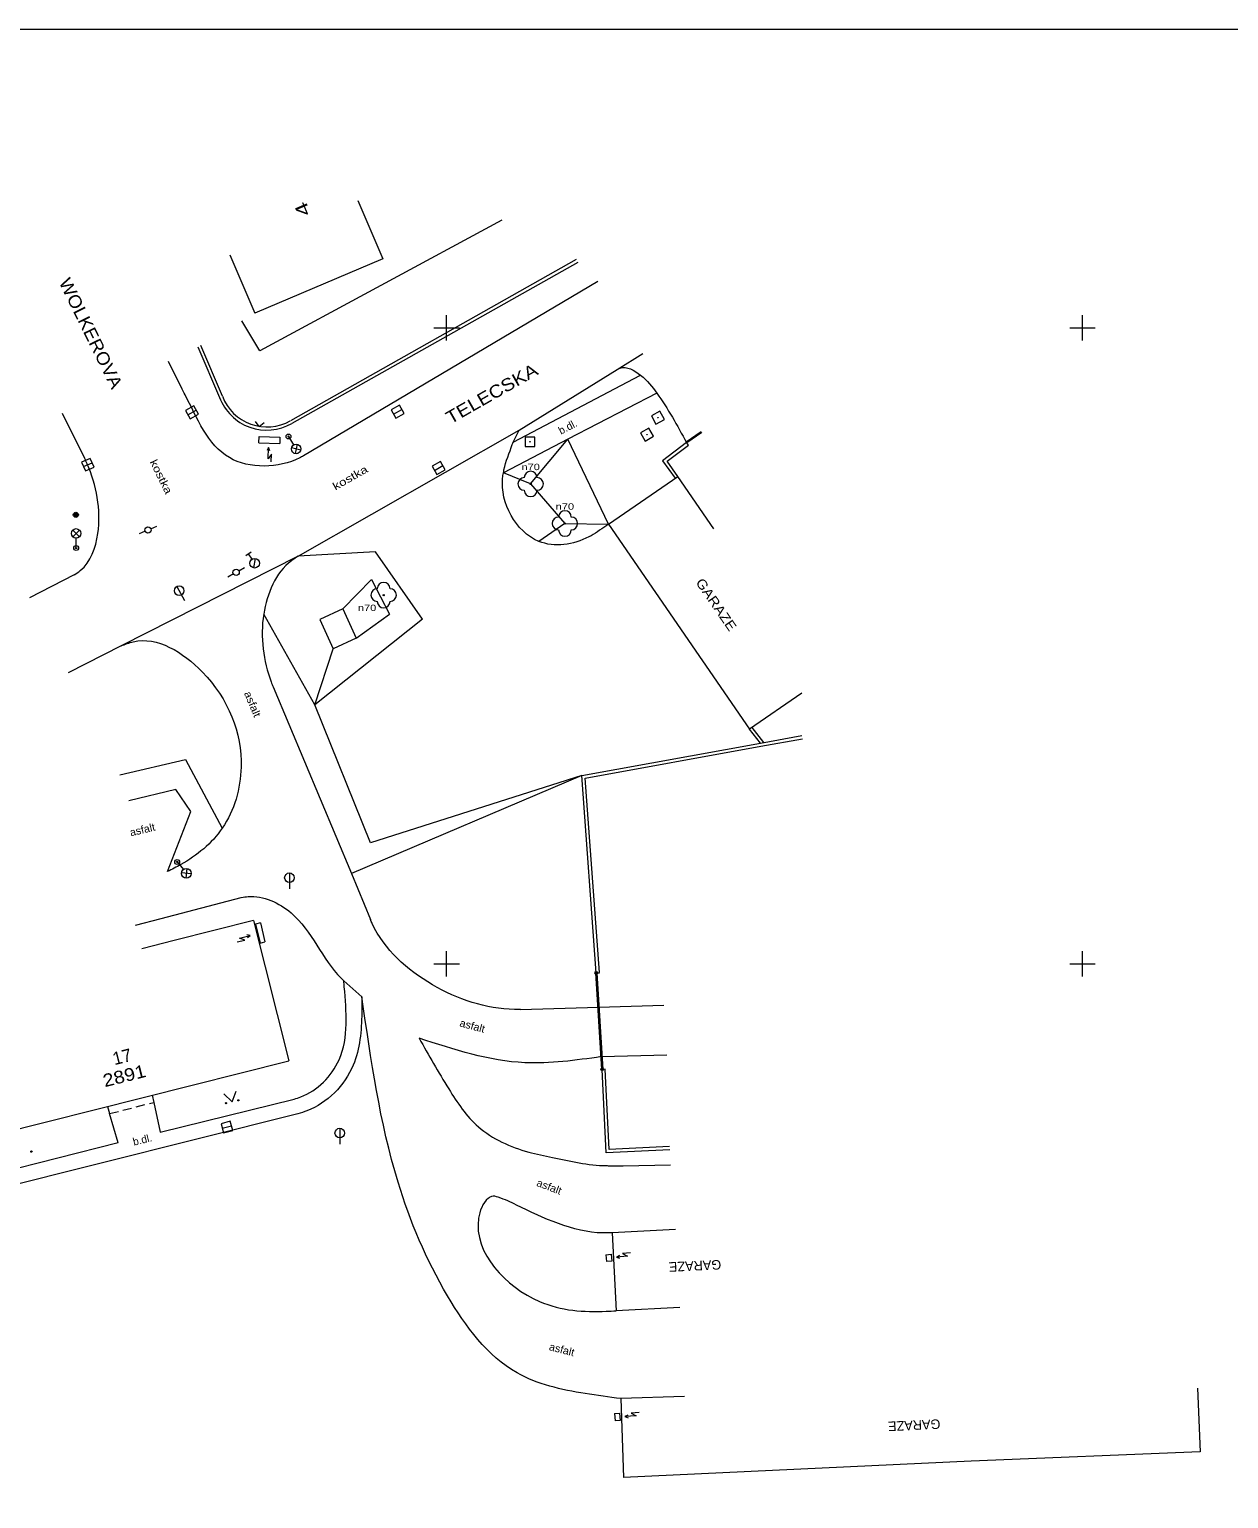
# Model space of a CAD drawing. Extents: x -670514 to -669423, y -1130798 to -1130123.
# Drawn here: x -669732.8 to -669638.5, y -1130592 to -1130476.5 of the extents above; entities that cross this region are included whole.
import ezdxf
from ezdxf.enums import TextEntityAlignment as Align

# ---------------------------------------------------------------- set-up
doc = ezdxf.new("R2010")
doc.units = 0
doc.header["$LTSCALE"] = 0.24
doc.linetypes.add('MEDIUM_DASHED', pattern=[4.5, 3, -1.5])
for name, color, linetype, lineweight in [('10', 7, 'Continuous', 13), ('11', 7, 'Continuous', 13), ('14', 7, 'Continuous', 13), ('22', 7, 'Continuous', 13), ('24', 7, 'Continuous', 13), ('25', 7, 'Continuous', 13), ('26', 7, 'Continuous', 13), ('27', 7, 'Continuous', 13), ('28', 7, 'Continuous', 13), ('33', 7, 'Continuous', 13), ('36', 7, 'Continuous', 13), ('45', 7, 'Continuous', 13), ('5', 7, 'Continuous', 13), ('60', 7, 'Continuous', 13), ('61', 7, 'Continuous', 13), ('7', 7, 'Continuous', 13), ('8', 7, 'Continuous', 13)]:
    doc.layers.add(name, color=color, linetype=linetype, lineweight=lineweight)
for name, color, linetype in [('40', 7, 'Continuous'), ('41', 7, 'Continuous'), ('43', 7, 'Continuous'), ('44', 7, 'Continuous')]:
    doc.layers.add(name, color=color, linetype=linetype)

msp = doc.modelspace()

# ---------------------------------------------------------------- linework, layer by layer
at = {"layer": '10'}
for p, q in [((-669688.102, -1130496.354), (-669711.258, -1130510.061)), ((-669720.795, -1130504.819), (-669721.869, -1130502.635)), ((-669694.776, -1130508.979), (-669684.745, -1130503.722)), ((-669728.447, -1130510.274), (-669730.191, -1130506.73)), ((-669694.776, -1130508.979), (-669694.298, -1130508.049)), ((-669729.281, -1130519.412), (-669732.799, -1130521.237)), ((-669708.164, -1130522.099), (-669709.981, -1130522.935)), ((-669709.981, -1130522.935), (-669708.929, -1130525.221)), ((-669708.164, -1130522.099), (-669707.112, -1130524.385)), ((-669725.596, -1130525.002), (-669729.753, -1130527.108)), ((-669707.112, -1130524.385), (-669708.929, -1130525.221)), ((-669722.446, -1130546.433), (-669716.144, -1130544.784)), ((-669724.449, -1130546.957), (-669722.446, -1130546.433)), ((-669706.657, -1130552.601), (-669708.083, -1130551.338)), ((-669694.188, -1130553.588), (-669688.071, -1130553.405)), ((-669688.071, -1130553.405), (-669682.917, -1130553.254)), ((-669687.835, -1130557.295), (-669682.681, -1130557.144)), ((-669723.014, -1130560.889), (-669722.511, -1130563.235)), ((-669722.511, -1130563.235), (-669711.997, -1130560.63)), ((-669711.698, -1130561.786), (-669745.171, -1130570.199)), ((-669725.823, -1130564.08), (-669726.508, -1130561.775)), ((-669725.823, -1130564.08), (-669739.953, -1130567.648)), ((-669686.12, -1130565.865), (-669682.406, -1130565.789))]:
    msp.add_line(p, q, dxfattribs=at)
for points in [[(-669711.663, -1130517.944), (-669694.298, -1130508.049), (-669686.598, -1130503.267), (-669684.585, -1130502.017)], [(-669683.462, -1130505.137), (-669690.477, -1130508.762), (-669695.534, -1130511.41)], [(-669713.646, -1130528.219), (-669707.484, -1130542.904), (-669705.99, -1130546.512)], [(-669721.945, -1130542.74), (-669720.107, -1130538.016), (-669721.296, -1130536.292), (-669724.995, -1130537.187)]]:
    msp.add_lwpolyline(points, dxfattribs=at)
for points in [[(-669686.598, -1130503.267), (-669686.363, -1130503.165), (-669684.745, -1130503.722), (-669683.462, -1130505.137), (-669681.135, -1130509.021)], [(-669711.258, -1130510.061), (-669711.553, -1130510.22), (-669717.079, -1130510.204), (-669720.565, -1130505.253), (-669720.795, -1130504.819)], [(-669695.534, -1130511.41), (-669695.491, -1130511.167), (-669694.837, -1130509.163), (-669694.776, -1130508.979)], [(-669729.281, -1130519.412), (-669728.799, -1130519.083), (-669727.424, -1130516.177), (-669728.268, -1130510.678), (-669728.447, -1130510.274)], [(-669711.663, -1130517.944), (-669712.193, -1130518.304), (-669714.38, -1130522.51), (-669713.792, -1130527.841), (-669713.646, -1130528.219)], [(-669725.596, -1130525.002), (-669724.632, -1130524.675), (-669719.212, -1130527.048), (-669716.159, -1130534.541), (-669717.636, -1130539.328), (-669720.902, -1130542.201), (-669721.945, -1130542.74)], [(-669716.144, -1130544.784), (-669715.597, -1130544.712), (-669712.232, -1130545.988), (-669708.293, -1130551.134), (-669708.083, -1130551.338)], [(-669694.188, -1130553.588), (-669694.674, -1130553.583), (-669701.117, -1130551.645), (-669705.847, -1130546.83), (-669705.99, -1130546.512)], [(-669711.997, -1130560.63), (-669711.461, -1130560.457), (-669708.461, -1130557.551), (-669708.045, -1130551.818), (-669708.083, -1130551.338)], [(-669706.657, -1130552.601), (-669706.669, -1130553.849), (-669707.347, -1130557.964), (-669710.982, -1130561.555), (-669711.698, -1130561.786)], [(-669686.299, -1130584.174), (-669689.11, -1130583.785), (-669694.463, -1130582.153), (-669699.923, -1130576.108), (-669703.819, -1130567.151), (-669706.657, -1130552.601)], [(-669687.835, -1130557.295), (-669693.851, -1130557.774), (-669702.163, -1130555.848)], [(-669702.163, -1130555.848), (-669699.833, -1130559.827), (-669697.503, -1130562.81), (-669693.548, -1130564.792), (-669691.672, -1130565.223), (-669687.451, -1130565.863), (-669687.307, -1130565.865), (-669686.12, -1130565.865)], [(-669686.995, -1130571.148), (-669687.709, -1130571.155), (-669694.508, -1130568.96), (-669695.936, -1130568.345), (-669696.459, -1130568.276), (-669696.717, -1130568.432), (-669697.488, -1130570.002), (-669692.7, -1130576.54), (-669687.448, -1130577.31), (-669686.669, -1130577.271)]]:
    msp.add_spline(points, degree=3, dxfattribs=at)
at = {"layer": '11'}
msp.add_line((-669711.663, -1130517.944), (-669725.596, -1130525.002), dxfattribs=at)
at = {"layer": '14'}
for p, q in [((-669693.393, -1130512.271), (-669690.477, -1130508.762)), ((-669687.272, -1130515.442), (-669690.477, -1130508.762)), ((-669693.393, -1130512.271), (-669695.534, -1130511.41)), ((-669693.393, -1130512.271), (-669690.702, -1130515.38)), ((-669690.702, -1130515.38), (-669692.762, -1130516.783)), ((-669690.702, -1130515.38), (-669687.272, -1130515.442)), ((-669705.896, -1130519.79), (-669708.164, -1130522.099)), ((-669705.896, -1130519.79), (-669704.48, -1130522.5)), ((-669710.365, -1130529.624), (-669714.38, -1130522.51)), ((-669701.907, -1130522.898), (-669710.365, -1130529.624)), ((-669707.112, -1130524.385), (-669704.48, -1130522.5)), ((-669689.367, -1130535.203), (-669707.484, -1130542.904))]:
    msp.add_line(p, q, dxfattribs=at)
for points in [[(-669695.671, -1130491.534), (-669714.69, -1130501.81), (-669716.107, -1130499.438)], [(-669701.907, -1130522.898), (-669705.601, -1130517.602), (-669711.663, -1130517.944)], [(-669689.367, -1130535.203), (-669705.996, -1130540.491), (-669710.365, -1130529.624), (-669708.929, -1130525.221)], [(-669725.686, -1130535.137), (-669720.522, -1130533.934), (-669717.636, -1130539.328)]]:
    msp.add_lwpolyline(points, dxfattribs=at)
msp.add_spline([(-669687.272, -1130515.442), (-669687.476, -1130515.58), (-669688.822, -1130516.433), (-669692.762, -1130516.783), (-669695.596, -1130511.824), (-669695.534, -1130511.41)], degree=3, dxfattribs=at)
at = {"layer": '22'}
for centre in [(-669693.393, -1130512.271), (-669690.702, -1130515.38), (-669704.949, -1130521.011)]:
    msp.add_circle(centre, 0.05, dxfattribs=at)
for centre, start, end in [((-669693.393, -1130511.771), 0, 180), ((-669693.893, -1130512.271), 90, 270), ((-669692.893, -1130512.271), 270, 90), ((-669693.393, -1130512.771), 180, 0), ((-669690.702, -1130514.88), 0, 180), ((-669691.202, -1130515.38), 90, 270), ((-669690.702, -1130515.88), 180, 0), ((-669690.202, -1130515.38), 270, 90), ((-669705.449, -1130521.011), 90, 270), ((-669704.949, -1130520.511), 0, 180), ((-669704.449, -1130521.011), 270, 90), ((-669704.949, -1130521.511), 180, 0)]:
    msp.add_arc(centre, 0.5, start, end, dxfattribs=at)
at = {"layer": '24'}
for p, q in [((-669714.766, -1130509.046), (-669713.125, -1130509.095)), ((-669714.645, -1130546.787), (-669714.282, -1130548.278)), ((-669687.474, -1130572.863), (-669687.422, -1130573.41)), ((-669686.796, -1130585.356), (-669686.76, -1130585.927))]:
    msp.add_line(p, q, dxfattribs=at)
for points in [[(-669714.765, -1130509.046), (-669714.751, -1130508.546), (-669713.11, -1130508.595), (-669713.125, -1130509.094)], [(-669713.901, -1130509.659), (-669714.004, -1130509.411), (-669714.121, -1130509.653)], [(-669713.788, -1130510.544), (-669713.769, -1130509.918), (-669714.03, -1130510.286), (-669714.004, -1130509.411)], [(-669714.645, -1130546.787), (-669715.033, -1130546.881), (-669714.669, -1130548.373), (-669714.282, -1130548.278)], [(-669716.47, -1130548.28), (-669715.861, -1130548.131), (-669716.285, -1130547.977), (-669715.435, -1130547.77)], [(-669715.647, -1130547.935), (-669715.435, -1130547.77), (-669715.699, -1130547.721)], [(-669687.473, -1130572.863), (-669687.075, -1130572.825), (-669687.023, -1130573.372), (-669687.422, -1130573.409)], [(-669685.554, -1130572.705), (-669686.177, -1130572.764), (-669685.78, -1130572.977), (-669686.651, -1130573.06)], [(-669686.418, -1130572.927), (-669686.651, -1130573.06), (-669686.397, -1130573.146)], [(-669684.871, -1130585.271), (-669685.496, -1130585.31), (-669685.106, -1130585.536), (-669685.979, -1130585.591)], [(-669686.795, -1130585.356), (-669686.396, -1130585.33), (-669686.36, -1130585.901), (-669686.76, -1130585.926)], [(-669685.741, -1130585.466), (-669685.979, -1130585.591), (-669685.728, -1130585.685)]]:
    msp.add_lwpolyline(points, dxfattribs=at)
at = {"layer": '25'}
for centre, radius in [((-669729.15, -1130514.7), 0.2), ((-669729.15, -1130514.7), 0.16), ((-669729.15, -1130514.7), 0.12), ((-669729.15, -1130514.7), 0.08), ((-669729.15, -1130514.7), 0.04), ((-669688.235, -1130550.71), 0.1002), ((-669688.235, -1130550.71), 0.0348), ((-669687.774, -1130558.293), 0.1002), ((-669687.774, -1130558.293), 0.0348)]:
    msp.add_circle(centre, radius, dxfattribs=at)
at = {"layer": '26'}
for points in [[(-669683.54, -1130507.566), (-669682.882, -1130507.206), (-669683.242, -1130506.548), (-669683.9, -1130506.908)], [(-669684.378, -1130508.905), (-669683.732, -1130508.525), (-669684.112, -1130507.879), (-669684.758, -1130508.259)], [(-669693.817, -1130509.331), (-669693.067, -1130509.331), (-669693.067, -1130508.581), (-669693.817, -1130508.581)]]:
    msp.add_lwpolyline(points, close=True, dxfattribs=at)
for centre in [(-669683.391, -1130507.057), (-669693.4419, -1130508.956), (-669684.245, -1130508.392)]:
    msp.add_circle(centre, 0.02, dxfattribs=at)
at = {"layer": '27'}
for p, q in [((-669720.35, -1130506.829), (-669719.694, -1130506.467)), ((-669704.171, -1130506.78), (-669703.519, -1130506.41)), ((-669728.552, -1130510.912), (-669727.868, -1130510.606)), ((-669700.944, -1130511.204), (-669700.294, -1130510.83)), ((-669721.205, -1130520.334), (-669720.614, -1130521.435)), ((-669712.359, -1130542.853), (-669712.359, -1130544.103)), ((-669717.639, -1130562.929), (-669716.913, -1130562.741)), ((-669708.404, -1130562.925), (-669708.398, -1130564.175))]:
    msp.add_line(p, q, dxfattribs=at)
for points in [[(-669720.17, -1130507.157), (-669719.513, -1130506.794), (-669719.875, -1130506.138), (-669720.532, -1130506.5)], [(-669703.986, -1130507.105), (-669703.334, -1130506.735), (-669703.704, -1130506.083), (-669704.357, -1130506.453)], [(-669728.4, -1130511.253), (-669727.715, -1130510.948), (-669728.021, -1130510.263), (-669728.706, -1130510.568)], [(-669700.757, -1130511.528), (-669700.107, -1130511.154), (-669700.482, -1130510.504), (-669701.132, -1130510.878)], [(-669717.546, -1130563.291), (-669716.819, -1130563.102), (-669717.008, -1130562.377), (-669717.733, -1130562.566)]]:
    msp.add_lwpolyline(points, close=True, dxfattribs=at)
for centre in [(-669721.0276, -1130520.6639), (-669712.3586, -1130543.2281), (-669708.4016, -1130563.3001)]:
    msp.add_circle(centre, 0.375, dxfattribs=at)
at = {"layer": '28'}
for p, q in [((-669723.71, -1130515.995), (-669724.169, -1130516.192)), ((-669723.25, -1130515.797), (-669722.791, -1130515.6)), ((-669715.796, -1130517.892), (-669715.379, -1130517.618)), ((-669715.299, -1130518.194), (-669715.588, -1130517.755)), ((-669715.169, -1130518.874), (-669715.017, -1130518.14)), ((-669716.766, -1130519.348), (-669717.199, -1130519.599)), ((-669716.334, -1130519.098), (-669715.901, -1130518.847))]:
    msp.add_line(p, q, dxfattribs=at)
for centre, radius in [((-669723.4801, -1130515.8963), 0.25), ((-669715.093, -1130518.507), 0.375), ((-669716.5501, -1130519.2233), 0.25)]:
    msp.add_circle(centre, radius, dxfattribs=at)
at = {"layer": '33'}
for p, q in [((-669712.428, -1130508.538), (-669712.026, -1130509.2)), ((-669711.467, -1130509.609), (-669712.195, -1130509.432)), ((-669711.742, -1130509.156), (-669711.92, -1130509.885)), ((-669729.393, -1130515.894), (-669728.863, -1130516.424)), ((-669729.393, -1130516.424), (-669728.863, -1130515.894)), ((-669729.128, -1130517.309), (-669729.128, -1130516.534)), ((-669721.187, -1130541.989), (-669720.699, -1130542.591)), ((-669720.424, -1130542.51), (-669720.503, -1130543.256)), ((-669720.091, -1130542.922), (-669720.836, -1130542.844))]:
    msp.add_line(p, q, dxfattribs=at)
for centre, radius in [((-669712.428, -1130508.538), 0.19), ((-669712.428, -1130508.538), 0.05), ((-669711.8307, -1130509.5207), 0.375), ((-669729.128, -1130516.159), 0.375), ((-669729.128, -1130517.309), 0.19), ((-669729.128, -1130517.309), 0.05), ((-669721.187, -1130541.989), 0.19), ((-669721.187, -1130541.989), 0.05), ((-669720.4636, -1130542.883), 0.375)]:
    msp.add_circle(centre, radius, dxfattribs=at)
at = {"layer": '36'}
msp.add_lwpolyline([(-669717.517, -1130560.222), (-669716.863, -1130560.842), (-669716.543, -1130560)], dxfattribs=at)
for centre in [(-669717.3505, -1130560.9533), (-669716.3755, -1130560.7307), (-669732.6426, -1130564.7555)]:
    msp.add_circle(centre, 0.05, dxfattribs=at)
at = {"layer": '5'}
for p, q in [((-669706.98, -1130489.981), (-669705.025, -1130494.583)), ((-669717.046, -1130494.256), (-669715.091, -1130498.858)), ((-669705.025, -1130494.583), (-669715.091, -1130498.858)), ((-669687.272, -1130515.442), (-669681.812, -1130511.686)), ((-669678.978, -1130515.805), (-669681.812, -1130511.686)), ((-669687.272, -1130515.442), (-669676.179, -1130531.556)), ((-669672.061, -1130528.721), (-669676.179, -1130531.556)), ((-669715.175, -1130546.584), (-669721.43, -1130548.169)), ((-669715.175, -1130546.584), (-669712.41, -1130557.622)), ((-669721.43, -1130548.169), (-669723.97, -1130548.813)), ((-669744.115, -1130565.589), (-669712.41, -1130557.622)), ((-669723.156, -1130560.322), (-669723.014, -1130560.889)), ((-669726.652, -1130561.201), (-669726.508, -1130561.775)), ((-669682.002, -1130570.882), (-669686.995, -1130571.148)), ((-669686.995, -1130571.148), (-669686.669, -1130577.271)), ((-669681.676, -1130577.005), (-669686.669, -1130577.271)), ((-669681.302, -1130584.004), (-669686.299, -1130584.174)), ((-669640.969, -1130583.365), (-669640.764, -1130588.361)), ((-669686.299, -1130584.174), (-669686.088, -1130590.385))]:
    msp.add_line(p, q, dxfattribs=at)
at = {"layer": '5', "linetype": 'MEDIUM_DASHED'}
msp.add_line((-669726.508, -1130561.775), (-669723.014, -1130560.889), dxfattribs=at)
at = {"layer": '5'}
msp.add_lwpolyline([(-669640.764, -1130588.361), (-669658.764, -1130589.1), (-669686.088, -1130590.385)], dxfattribs=at)
at = {"layer": '60'}
msp.add_lwpolyline([(-669833.172, -1130763.536), (-669423.172, -1130763.536), (-669423.172, -1130476.536), (-669833.172, -1130476.536)], close=True, dxfattribs=at)
at = {"layer": '61'}
for p, q in [((-669700, -1130501), (-669700, -1130499)), ((-669650, -1130501), (-669650, -1130499)), ((-669701, -1130500), (-669699, -1130500)), ((-669651, -1130500), (-669649, -1130500)), ((-669700, -1130551), (-669700, -1130549)), ((-669650, -1130551), (-669650, -1130549)), ((-669701, -1130550), (-669699, -1130550)), ((-669651, -1130550), (-669649, -1130550))]:
    msp.add_line(p, q, dxfattribs=at)
at = {"layer": '7'}
for p, q in [((-669689.811, -1130494.632), (-669712.286, -1130507.303)), ((-669689.689, -1130494.85), (-669712.164, -1130507.521)), ((-669719.548, -1130501.493), (-669717.849, -1130505.47)), ((-669717.619, -1130505.371), (-669719.318, -1130501.394)), ((-669714.728, -1130507.744), (-669715.037, -1130507.35)), ((-669714.728, -1130507.744), (-669714.334, -1130507.435)), ((-669682.647, -1130510.475), (-669680.986, -1130509.215)), ((-669681.812, -1130511.686), (-669682.647, -1130510.475)), ((-669675.049, -1130532.601), (-669675.972, -1130531.414)), ((-669675.327, -1130532.652), (-669672.059, -1130532.058)), ((-669687.451, -1130564.863), (-669687.774, -1130558.293)), ((-669682.457, -1130564.617), (-669687.451, -1130564.863))]:
    msp.add_line(p, q, dxfattribs=at)
for points in [[(-669681.138, -1130509.016), (-669683.024, -1130510.447), (-669682.018, -1130511.828)], [(-669688.235, -1130550.71), (-669689.367, -1130535.203), (-669675.327, -1130532.652), (-669676.179, -1130531.556)], [(-669687.985, -1130550.691), (-669689.101, -1130535.408), (-669675.282, -1130532.897), (-669672.014, -1130532.303)], [(-669682.469, -1130564.367), (-669687.213, -1130564.601), (-669687.524, -1130558.28)]]:
    msp.add_lwpolyline(points, dxfattribs=at)
for radius in [3.973, 3.723]:
    msp.add_arc((-669714.1311, -1130504.0691), radius, 200.64623, 299.67752, dxfattribs=at)
at = {"layer": '8', "lineweight": 35}
for p, q in [((-669679.948, -1130508.204), (-669681.135, -1130509.021)), ((-669688.235, -1130550.71), (-669687.774, -1130558.293))]:
    msp.add_line(p, q, dxfattribs=at)
at = {"layer": '8'}
for p, q in [((-669680.993, -1130509.226), (-669681.135, -1130509.021)), ((-669688.235, -1130550.71), (-669687.985, -1130550.694)), ((-669687.524, -1130558.277), (-669687.774, -1130558.293))]:
    msp.add_line(p, q, dxfattribs=at)

# ---------------------------------------------------------------- texts
at = {"layer": '22', "width": 1.3}
for p in [(-669693.3925, -1130511.185), (-669690.7015, -1130514.294), (-669706.2545, -1130522.261)]:
    msp.add_text('n70', height=0.499, dxfattribs=at).set_placement(p, align=Align.CENTER)
at = {"layer": '40'}
for rotation, p in [(27.328, (-669690.3402, -1130508.0515)), (14.108, (-669723.8471, -1130564.1176))]:
    msp.add_text('b.dl.', height=0.6, rotation=rotation, dxfattribs=at).set_placement(p, align=Align.CENTER)
for s, rotation, width, p in [('kostka', 296.202, 1.25, (-669722.7161, -1130511.833)), ('kostka', 29.676, 1.3, (-669707.4375, -1130512.0399)), ('asfalt', 292.763, 1.1, (-669715.5342, -1130529.6929)), ('asfalt', 13.602, 1.05, (-669723.8491, -1130539.7437)), ('asfalt', 344.963, 1.05, (-669698.0528, -1130555.1614)), ('asfalt', 339.276, 1.05, (-669692.0402, -1130567.7964)), ('asfalt', 345.501, 1.05, (-669691.0166, -1130580.606))]:
    msp.add_text(s, height=0.6, rotation=rotation, dxfattribs=dict(at, width=width)).set_placement(p, align=Align.CENTER)
at = {"layer": '41', "width": 1.15}
msp.add_text('GARAZE', height=0.75, rotation=304.544, dxfattribs=at).set_placement((-669679.1097, -1130521.9674), align=Align.CENTER)
at = {"layer": '41'}
for p in [(-669680.4889, -1130573.3642), (-669663.2569, -1130585.8942)]:
    msp.add_text('GARAZE', height=0.75, rotation=182.693, dxfattribs=at).set_placement(p, align=Align.CENTER)
at = {"layer": '43', "width": 1.15}
msp.add_text('2891', height=1, rotation=14.064, dxfattribs=at).set_placement((-669725.2155, -1130559.28), align=Align.CENTER)
at = {"layer": '44', "width": 1.5}
msp.add_text('4', height=1, rotation=113.011, dxfattribs=at).set_placement((-669710.8735, -1130490.4955), align=Align.CENTER)
at = {"layer": '44'}
msp.add_text('17', height=1, rotation=14.064, dxfattribs=at).set_placement((-669725.395, -1130557.7864), align=Align.CENTER)
at = {"layer": '45'}
for s, rotation, width, p in [('WOLKEROVA', 296.202, 1.1, (-669728.4227, -1130500.6487)), ('TELECSKA', 29.676, 1.15, (-669696.2055, -1130505.61))]:
    msp.add_text(s, height=1, rotation=rotation, dxfattribs=dict(at, width=width)).set_placement(p, align=Align.CENTER)

doc.saveas('drawing.dxf')
